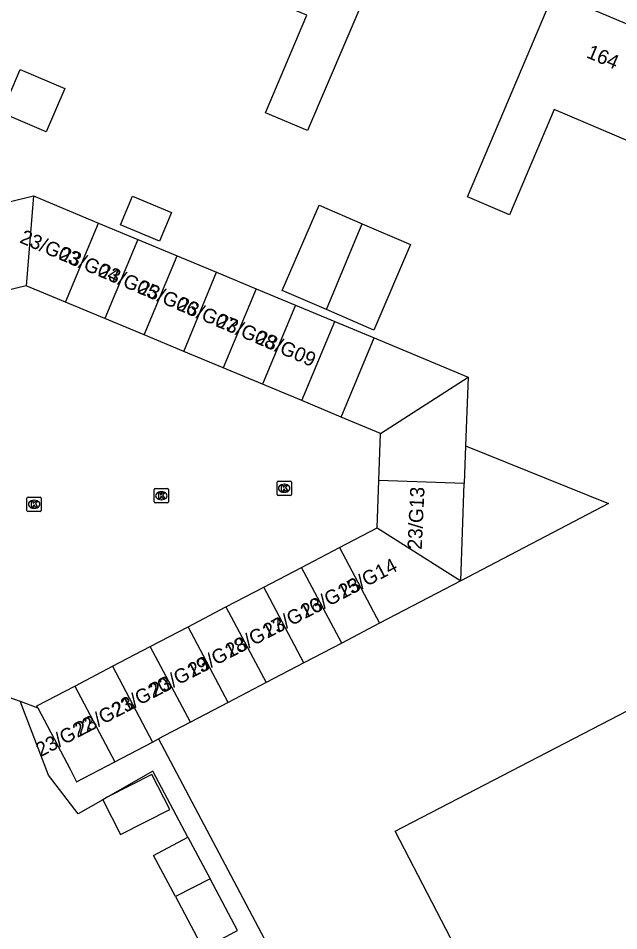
# Model space of a CAD drawing. Extents: x 162074 to 163034, y 381824 to 382557.
# Drawn here: x 162519.2 to 162561.2, y 382392.7 to 382456.5 of the extents above; entities that cross this region are included whole.
import ezdxf

# ---------------------------------------------------------------- set-up
doc = ezdxf.new("R2010")
doc.units = 0
for name, color, linetype in [('IMGEO_Kolk', 7, 'Continuous'), ('IMGEO_Pand', 7, 'Continuous'), ('IMGEO_Pand_nummerreeks', 7, 'Continuous'), ('IMGEO_Rijbaan_lokaal_open', 7, 'Continuous'), ('IMGEO_Voetpad_open', 7, 'Continuous')]:
    doc.layers.add(name, color=color, linetype=linetype)

msp = doc.modelspace()

# ---------------------------------------------------------------- linework, layer by layer
at = {"layer": 'IMGEO_Kolk'}
for p, q in [((162528.712, 382422.667), (162528.712, 382423.519)), ((162528.787, 382423.593), (162529.639, 382423.593)), ((162529.713, 382423.519), (162529.713, 382422.667)), ((162537.298, 382423.19), (162537.298, 382424.042)), ((162537.373, 382424.116), (162538.225, 382424.116)), ((162537.786, 382423.896), (162537.811, 382423.896)), ((162538.299, 382424.042), (162538.299, 382423.19)), ((162519.82, 382422.07), (162519.82, 382422.922)), ((162519.895, 382422.996), (162520.747, 382422.996)), ((162520.821, 382422.922), (162520.821, 382422.07)), ((162529.2, 382423.373), (162529.225, 382423.373)), ((162538.225, 382423.116), (162537.373, 382423.116)), ((162537.809, 382423.336), (162537.784, 382423.336)), ((162520.308, 382422.776), (162520.333, 382422.776)), ((162529.639, 382422.593), (162528.787, 382422.593)), ((162529.223, 382422.813), (162529.198, 382422.813)), ((162520.747, 382421.996), (162519.895, 382421.996)), ((162520.331, 382422.216), (162520.306, 382422.216))]:
    msp.add_line(p, q, dxfattribs=at)
for points in [[(162528.712, 382422.667), (162528.712, 382423.519)], [(162528.787, 382423.593), (162529.639, 382423.593)], [(162529.713, 382423.519), (162529.713, 382422.667)], [(162537.298, 382423.19), (162537.298, 382424.042)], [(162537.373, 382424.116), (162538.225, 382424.116)], [(162537.619, 382423.816), (162537.742, 382423.816), (162537.742, 382423.665), (162537.872, 382423.816), (162538.036, 382423.816), (162537.89, 382423.665), (162538.043, 382423.416), (162537.891, 382423.416), (162537.806, 382423.58), (162537.742, 382423.513), (162537.742, 382423.416), (162537.619, 382423.416), (162537.619, 382423.816)], [(162538.299, 382424.042), (162538.299, 382423.19)], [(162519.82, 382422.07), (162519.82, 382422.922)], [(162519.895, 382422.996), (162520.747, 382422.996)], [(162520.821, 382422.922), (162520.821, 382422.07)], [(162529.033, 382423.293), (162529.156, 382423.293), (162529.156, 382423.142), (162529.286, 382423.293), (162529.45, 382423.293), (162529.304, 382423.142), (162529.457, 382422.893), (162529.305, 382422.893), (162529.22, 382423.057), (162529.156, 382422.99), (162529.156, 382422.893), (162529.033, 382422.893), (162529.033, 382423.293)], [(162538.225, 382423.116), (162537.373, 382423.116)], [(162520.141, 382422.696), (162520.264, 382422.696), (162520.264, 382422.545), (162520.394, 382422.696), (162520.558, 382422.696), (162520.412, 382422.545), (162520.565, 382422.296), (162520.413, 382422.296), (162520.328, 382422.46), (162520.264, 382422.393), (162520.264, 382422.296), (162520.141, 382422.296), (162520.141, 382422.696)], [(162529.639, 382422.593), (162528.787, 382422.593)], [(162520.747, 382421.996), (162519.895, 382421.996)]]:
    msp.add_lwpolyline(points, dxfattribs=at)
for centre, start, end in [((162528.789, 382423.517), 91.55205, 178.44795), ((162528.789, 382423.517), 91.55205, 178.44795), ((162529.637, 382423.517), 1.55205, 88.44795), ((162529.637, 382423.517), 1.55205, 88.44795), ((162537.375, 382424.04), 91.55205, 178.44795), ((162537.375, 382424.04), 91.55205, 178.44795), ((162538.223, 382424.04), 1.55205, 88.44795), ((162538.223, 382424.04), 1.55205, 88.44795), ((162519.897, 382422.92), 91.55205, 178.44795), ((162519.897, 382422.92), 91.55205, 178.44795), ((162520.745, 382422.92), 1.55205, 88.44795), ((162520.745, 382422.92), 1.55205, 88.44795), ((162537.375, 382423.192), 181.55205, 268.44795), ((162537.375, 382423.192), 181.55205, 268.44795), ((162538.223, 382423.192), 271.55205, 358.44795), ((162538.223, 382423.192), 271.55205, 358.44795), ((162528.789, 382422.669), 181.55205, 268.44795), ((162528.789, 382422.669), 181.55205, 268.44795), ((162529.637, 382422.669), 271.55205, 358.44795), ((162529.637, 382422.669), 271.55205, 358.44795), ((162519.897, 382422.072), 181.55205, 268.44795), ((162519.897, 382422.072), 181.55205, 268.44795), ((162520.745, 382422.072), 271.55205, 358.44795), ((162520.745, 382422.072), 271.55205, 358.44795)]:
    msp.add_arc(centre, 0.0765, start, end, dxfattribs=at)
for centre, major_axis, ratio, start_param, end_param in [((162537.785, 382423.616), (-0.387, 0.002), 0.722429, 4.712389, 7.853982), ((162537.81, 382423.616), (-0.39, 0.002), 0.717154, 1.570796, 4.712389), ((162529.199, 382423.093), (-0.387, 0.002), 0.722429, 4.712389, 7.853982), ((162529.224, 382423.093), (-0.39, 0.002), 0.717154, 1.570796, 4.712389), ((162520.307, 382422.496), (-0.387, 0.002), 0.722429, 4.712389, 7.853982), ((162520.332, 382422.496), (-0.39, 0.002), 0.717154, 1.570796, 4.712389)]:
    msp.add_ellipse(centre, major_axis=major_axis, ratio=ratio, start_param=start_param, end_param=end_param, dxfattribs=at)
at = {"layer": 'IMGEO_Pand'}
for points in [[(162536.214, 382466.853), (162545.458, 382462.933), (162544.778, 382461.328), (162545.416, 382461.057), (162544.064, 382457.868), (162543.471, 382458.119), (162539.438, 382448.608), (162536.492, 382449.857), (162539.383, 382456.674), (162538.978, 382456.846), (162533.041, 382459.363)], [(162563.083, 382447.37), (162556.671, 382450.088), (162553.548, 382442.722), (162550.601, 382443.971), (162554.7, 382453.638), (162556.651, 382458.241), (162566.01, 382454.273)], [(162518.056, 382449.845), (162519.344, 382452.87), (162522.461, 382451.542), (162521.173, 382448.518), (162518.056, 382449.845)], [(162515.42, 382442.864), (162520.267, 382444.049)], [(162520.267, 382444.049), (162519.767, 382437.772)], [(162520.267, 382444.049), (162524.823, 382442.149)], [(162526.347, 382442.014), (162527.188, 382444.031), (162529.921, 382442.891), (162529.08, 382440.874), (162526.347, 382442.014)], [(162540.749, 382436.096), (162537.663, 382437.426), (162540.235, 382443.395), (162543.246, 382442.097)], [(162522.519, 382436.625), (162524.823, 382442.149)], [(162524.823, 382442.149), (162527.574, 382441.002)], [(162543.246, 382442.097), (162546.629, 382440.64), (162544.057, 382434.671), (162540.749, 382436.096)], [(162540.749, 382436.096), (162542.881, 382441.212), (162543.246, 382442.097)], [(162527.574, 382441.002), (162525.271, 382435.477)], [(162527.574, 382441.002), (162530.326, 382439.854)], [(162528.022, 382434.33), (162530.326, 382439.854)], [(162530.326, 382439.854), (162533.078, 382438.707)], [(162530.774, 382433.182), (162533.078, 382438.707)], [(162533.078, 382438.707), (162535.83, 382437.56)], [(162519.767, 382437.772), (162516.84, 382437.056)], [(162522.519, 382436.625), (162519.767, 382437.772)], [(162535.83, 382437.56), (162533.526, 382432.035)], [(162535.83, 382437.56), (162538.581, 382436.412)], [(162525.271, 382435.477), (162522.519, 382436.625)], [(162538.581, 382436.412), (162536.278, 382430.887)], [(162538.581, 382436.412), (162541.333, 382435.265)], [(162528.022, 382434.33), (162525.271, 382435.477)], [(162539.029, 382429.74), (162541.333, 382435.265)], [(162541.333, 382435.265), (162544.085, 382434.117)], [(162530.774, 382433.182), (162528.022, 382434.33)], [(162541.781, 382428.592), (162544.085, 382434.117)], [(162544.085, 382434.117), (162550.649, 382431.38)], [(162533.526, 382432.035), (162530.774, 382433.182)], [(162536.278, 382430.887), (162533.526, 382432.035)], [(162544.533, 382427.445), (162550.649, 382431.38)], [(162550.649, 382431.38), (162550.479, 382426.575)], [(162539.029, 382429.74), (162536.278, 382430.887)], [(162541.781, 382428.592), (162539.029, 382429.74)], [(162544.533, 382427.445), (162541.781, 382428.592)], [(162544.416, 382424.15), (162544.533, 382427.445)], [(162550.479, 382426.575), (162560.476, 382422.56), (162550.145, 382417.154)], [(162550.479, 382426.575), (162550.385, 382423.938)], [(162544.3, 382420.854), (162544.416, 382424.15)], [(162550.385, 382423.938), (162544.416, 382424.15)], [(162550.145, 382417.154), (162550.385, 382423.938)], [(162541.657, 382419.471), (162544.3, 382420.854)], [(162544.3, 382420.854), (162550.145, 382417.154)], [(162539.014, 382418.089), (162541.657, 382419.471)], [(162541.657, 382419.471), (162544.462, 382414.18)], [(162536.371, 382416.706), (162539.014, 382418.089)], [(162541.819, 382412.797), (162539.014, 382418.089)], [(162550.145, 382417.154), (162544.462, 382414.18)], [(162533.728, 382415.323), (162536.371, 382416.706)], [(162539.176, 382411.414), (162536.371, 382416.706)], [(162531.085, 382413.94), (162533.728, 382415.323)], [(162533.728, 382415.323), (162536.533, 382410.031)], [(162528.442, 382412.558), (162531.085, 382413.94)], [(162533.89, 382408.649), (162531.085, 382413.94)], [(162544.462, 382414.18), (162541.819, 382412.797)], [(162541.819, 382412.797), (162539.176, 382411.414)], [(162525.799, 382411.175), (162528.442, 382412.558)], [(162531.247, 382407.266), (162528.442, 382412.558)], [(162539.176, 382411.414), (162536.533, 382410.031)], [(162523.156, 382409.792), (162525.799, 382411.175)], [(162525.799, 382411.175), (162528.604, 382405.883)], [(162520.581, 382408.282), (162520.514, 382408.41), (162523.156, 382409.792)], [(162523.156, 382409.792), (162525.961, 382404.5)], [(162536.533, 382410.031), (162533.89, 382408.649)], [(162520.581, 382408.282), (162522.832, 382403.98), (162523.291, 382403.103), (162525.961, 382404.5)], [(162533.89, 382408.649), (162531.247, 382407.266)], [(162570.821, 382350.911), (162559.051, 382373.589), (162560.496, 382374.339), (162558.734, 382377.733), (162557.289, 382376.983), (162555.051, 382375.822), (162551.058, 382383.517), (162553.32, 382384.692), (162545.561, 382399.659), (162563.063, 382408.737)], [(162531.247, 382407.266), (162529.419, 382406.309), (162529.011, 382406.096)], [(162525.961, 382404.5), (162528.604, 382405.883)], [(162528.604, 382405.883), (162529.011, 382406.096)], [(162525.124, 382401.848), (162526.362, 382399.418), (162529.802, 382401.169), (162528.556, 382403.617), (162525.466, 382402.043)], [(162525.466, 382402.043), (162525.124, 382401.848)], [(162530.193, 382395.078), (162528.656, 382397.962), (162531.06, 382399.243)], [(162531.06, 382399.243), (162532.619, 382396.316)], [(162532.619, 382396.316), (162530.193, 382395.078)], [(162534.354, 382392.613), (162534.54, 382392.712), (162532.619, 382396.316)], [(162530.193, 382395.078), (162532.136, 382391.431), (162534.354, 382392.613)]]:
    msp.add_lwpolyline(points, dxfattribs=at)
at = {"layer": 'IMGEO_Rijbaan_lokaal_open'}
for points in [[(162513.191, 382407.718), (162518.098, 382409.172), (162519.34, 382408.727)], [(162519.34, 382408.727), (162520.581, 382408.282)]]:
    msp.add_lwpolyline(points, dxfattribs=at)
at = {"layer": 'IMGEO_Voetpad_open'}
for points in [[(162525.124, 382401.848), (162523.393, 382400.86), (162521.332, 382403.562), (162519.34, 382408.727)], [(162529.011, 382406.096), (162569.932, 382328.823)], [(162531.06, 382399.243), (162528.612, 382403.839), (162525.466, 382402.043)]]:
    msp.add_lwpolyline(points, dxfattribs=at)

# ---------------------------------------------------------------- texts
at = {"layer": 'IMGEO_Pand_nummerreeks'}
for s, rotation, p in [('164', 337.02307, (162558.864, 382453.739)), ('23/G03', 336.91822, (162519.249, 382440.807)), ('23/G04', 336.91822, (162521.992, 382439.638)), ('23/G05', 336.91822, (162524.736, 382438.469)), ('23/G06', 336.91822, (162527.479, 382437.3)), ('23/G07', 336.91822, (162530.222, 382436.131)), ('23/G08', 336.91822, (162532.968, 382434.961)), ('23/G09', 336.91822, (162535.705, 382433.794)), ('23/G13', 87.35745, (162547.41, 382419.31)), ('23/G14', 27.59354, (162541.911, 382415.865)), ('23/G15', 27.59354, (162539.279, 382414.489)), ('23/G16', 27.59354, (162536.648, 382413.114)), ('23/G17', 27.59354, (162534.017, 382411.739)), ('23/G18', 27.59354, (162531.389, 382410.365)), ('23/G19', 27.59354, (162528.752, 382408.987)), ('23/G20', 27.59365, (162526.046, 382407.572)), ('23/G21', 27.59354, (162523.509, 382406.247)), ('23/G22', 27.59354, (162520.774, 382404.818))]:
    msp.add_text(s, height=1, rotation=rotation, dxfattribs=at).set_placement(p)

doc.saveas('drawing.dxf')
